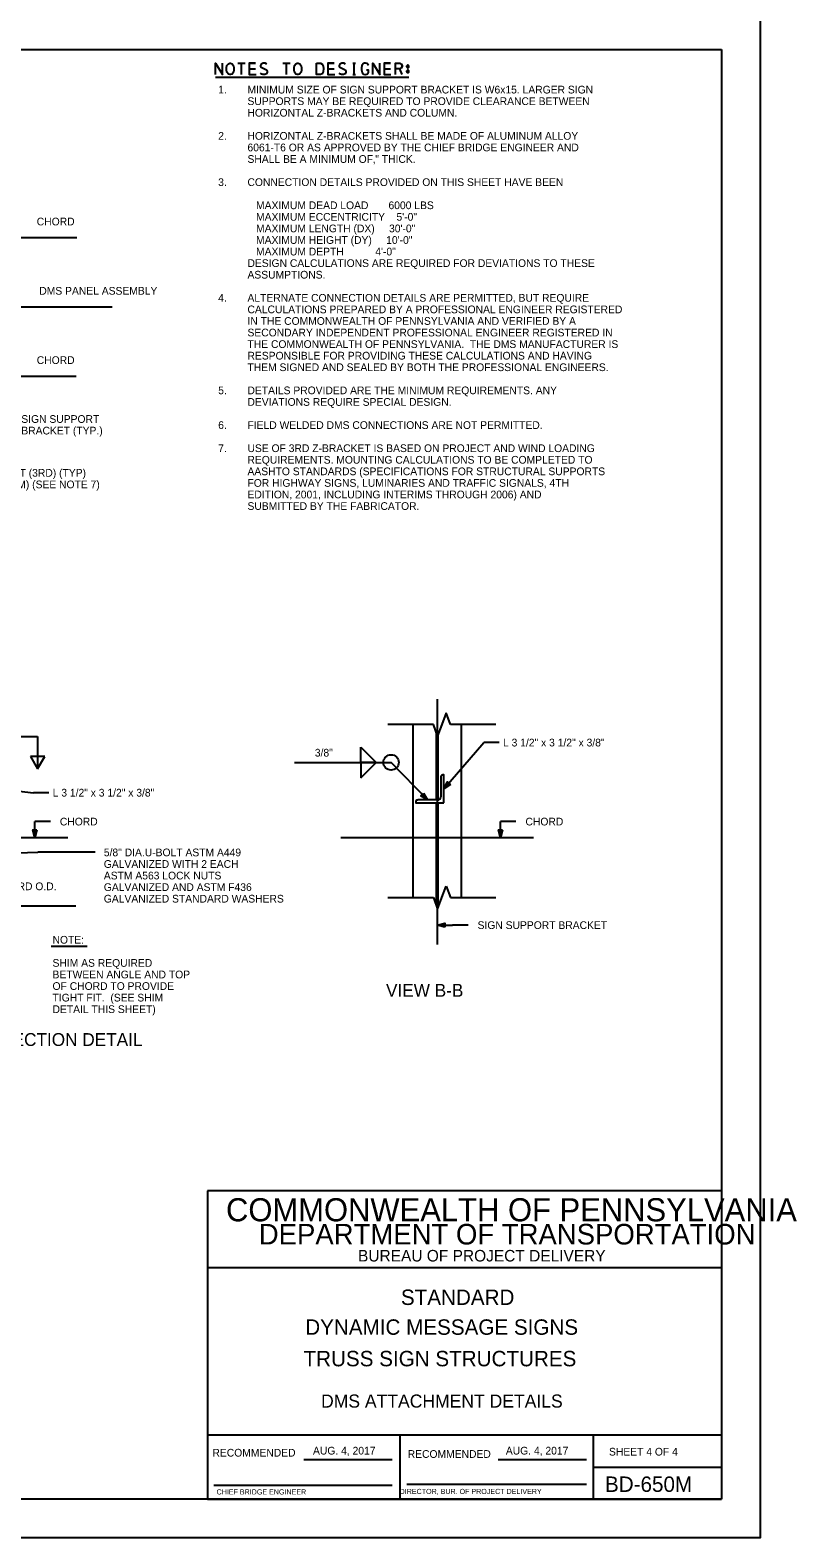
# Model space of a CAD drawing. Extents: x 3831399 to 3833095, y 499014 to 500202.
# Drawn here: x 3832797 to 3833095, y 499014 to 499601 of the extents above; entities that cross this region are included whole.
import ezdxf

# ---------------------------------------------------------------- set-up
doc = ezdxf.new("R2010")
doc.units = 0
for name, color, linetype in [('10', 7, 'Continuous'), ('2', 7, 'Continuous'), ('CNTR', 7, 'Continuous'), ('Default', 7, 'Continuous'), ('DIM TXT', 7, 'Continuous'), ('PLT-BNDY', 7, 'Continuous'), ('structure', 7, 'Continuous')]:
    doc.layers.add(name, color=color, linetype=linetype)

msp = doc.modelspace()

# ---------------------------------------------------------------- linework, layer by layer
at = {"layer": '2'}
for p, q in [((3832280.16, 499593.03), (3833066.16, 499593.03)), ((3833066.16, 499593.03), (3833066.16, 499029.03)), ((3833066.16, 499149.03), (3832866.16, 499149.03)), ((3832866.16, 499149.03), (3832866.16, 499029.03)), ((3833066.16, 499119.03), (3832866.16, 499119.03)), ((3833066.16, 499054.03), (3832866.16, 499054.03)), ((3832941.16, 499029.03), (3832941.16, 499054.03)), ((3833016.16, 499054.03), (3833016.16, 499029.03)), ((3832903.62, 499044.53), (3832938.03, 499044.53)), ((3832979.24, 499044.53), (3833013.65, 499044.53)), ((3833016.16, 499041.53), (3833066.16, 499041.53)), ((3832868.66, 499034.53), (3832938.03, 499034.53)), ((3832943.79, 499034.9), (3833013.65, 499034.9)), ((3833066.16, 499029.03), (3832280.16, 499029.03)), ((3832866.16, 499029.03), (3833066.16, 499029.03))]:
    msp.add_line(p, q, dxfattribs=at)
at = {"layer": 'CNTR'}
for p, q in [((3832528.61, 499519.83), (3832815.35, 499519.83)), ((3832528.61, 499492.88), (3832829.18, 499492.88)), ((3832528.61, 499465.92), (3832815.12, 499465.92)), ((3832955.53, 499340.29), (3832955.53, 499244.81)), ((3832685.4, 499286.41), (3832811.96, 499286.41)), ((3832918.03, 499286.41), (3832993.03, 499286.41))]:
    msp.add_line(p, q, dxfattribs=at)
at = {"layer": 'Default'}
for p, q in [((3832797.4, 499318), (3832800.15, 499313.23)), ((3832802.9, 499318), (3832797.4, 499318)), ((3832800.15, 499313.23), (3832802.9, 499318))]:
    msp.add_line(p, q, dxfattribs=at)
at = {"layer": 'DIM TXT'}
for p, q in [((3832878.01, 499587.65), (3832880.91, 499587.65)), ((3832879.46, 499583.28), (3832879.46, 499587.65)), ((3832879.46, 499583.28), (3832879.46, 499587.65)), ((3832882.39, 499587.65), (3832884.9, 499587.65)), ((3832895.51, 499587.65), (3832898.41, 499587.65)), ((3832896.96, 499583.28), (3832896.96, 499587.65)), ((3832896.96, 499583.28), (3832896.96, 499587.65)), ((3832913.01, 499587.65), (3832915.53, 499587.65)), ((3832922.73, 499587.65), (3832923.76, 499587.65)), ((3832923.24, 499583.28), (3832923.24, 499587.65)), ((3832934.89, 499587.65), (3832937.4, 499587.65)), ((3832869.26, 499582.28), (3832944.57, 499582.28)), ((3832882.39, 499585.48), (3832884.9, 499585.48)), ((3832882.39, 499585.48), (3832884.9, 499585.48)), ((3832913.01, 499585.48), (3832915.53, 499585.48)), ((3832913.01, 499585.48), (3832915.53, 499585.48)), ((3832922.73, 499583.28), (3832923.76, 499583.28)), ((3832934.89, 499585.48), (3832937.4, 499585.48)), ((3832934.89, 499585.48), (3832937.4, 499585.48)), ((3832941.98, 499583.28), (3832940.98, 499585.51)), ((3832959.06, 499334.99), (3832957.39, 499330.48)), ((3832960.72, 499330.48), (3832959.06, 499334.99)), ((3832954.05, 499330.48), (3832936.37, 499330.48)), ((3832955.72, 499325.97), (3832954.05, 499330.48)), ((3832957.39, 499330.48), (3832955.72, 499325.97)), ((3832978.4, 499330.48), (3832960.72, 499330.48)), ((3832787.65, 499325.73), (3832800.15, 499325.73)), ((3832800.15, 499325.73), (3832800.15, 499313.23)), ((3832958.13, 499305.36), (3832973.63, 499323.39)), ((3832979.63, 499323.39), (3832973.63, 499323.39)), ((3832925.85, 499321.67), (3832931.85, 499315.67)), ((3832925.85, 499315.67), (3832925.85, 499321.67)), ((3832900.11, 499315.67), (3832937.61, 499315.67)), ((3832931.85, 499315.67), (3832925.85, 499315.67)), ((3832925.85, 499309.67), (3832931.85, 499315.67)), ((3832931.85, 499315.67), (3832925.85, 499315.67)), ((3832925.85, 499315.67), (3832925.85, 499309.67)), ((3832951.82, 499301.06), (3832937.61, 499315.67)), ((3832777.66, 499306.31), (3832798.52, 499303.9)), ((3832804.51, 499303.9), (3832798.52, 499303.9)), ((3832799.1, 499286.41), (3832799.1, 499292.66)), ((3832805.1, 499292.66), (3832799.1, 499292.66)), ((3832980.16, 499286.41), (3832980.16, 499292.66)), ((3832986.16, 499292.66), (3832980.16, 499292.66)), ((3832782.09, 499280.23), (3832800.26, 499280.75)), ((3832822.52, 499280.75), (3832800.26, 499280.75)), ((3832957.39, 499263.08), (3832959.06, 499267.59)), ((3832959.06, 499267.59), (3832960.72, 499263.08)), ((3832814.96, 499259.75), (3832767.85, 499259.75)), ((3832936.37, 499263.08), (3832954.05, 499263.08)), ((3832954.05, 499263.08), (3832955.72, 499258.57)), ((3832955.72, 499258.57), (3832957.39, 499263.08)), ((3832960.72, 499263.08), (3832978.4, 499263.08)), ((3832955.53, 499252.33), (3832961.53, 499252.33)), ((3832967.53, 499252.33), (3832961.53, 499252.33)), ((3832805.41, 499244.16), (3832819.41, 499244.16))]:
    msp.add_line(p, q, dxfattribs=at)
for points in [[(3832869.26, 499583.28), (3832869.26, 499587.65), (3832871.99, 499583.28), (3832871.99, 499587.65)], [(3832874.88, 499587.65), (3832875.22, 499587.65), (3832875.81, 499587.41), (3832876.36, 499586.69), (3832876.5, 499585.82), (3832876.5, 499585.03), (3832876.36, 499584.17), (3832875.77, 499583.45), (3832875.22, 499583.28), (3832874.88, 499583.28), (3832874.36, 499583.45), (3832873.78, 499584.17), (3832873.64, 499585.03), (3832873.64, 499585.82), (3832873.78, 499586.72), (3832874.36, 499587.44), (3832874.88, 499587.65)], [(3832884.9, 499587.65), (3832882.39, 499587.65), (3832882.39, 499583.28), (3832885.08, 499583.28)], [(3832889.28, 499587.34), (3832888.59, 499587.65), (3832887.8, 499587.65), (3832887.07, 499587.34), (3832886.76, 499586.79), (3832886.76, 499586.58), (3832887.11, 499586.07), (3832889.11, 499585.03), (3832889.45, 499584.55), (3832889.42, 499584.14), (3832889.11, 499583.59), (3832888.52, 499583.28), (3832887.69, 499583.28), (3832887.31, 499583.41), (3832886.76, 499583.79)], [(3832901.13, 499587.65), (3832901.47, 499587.65), (3832902.06, 499587.41), (3832902.61, 499586.69), (3832902.75, 499585.82), (3832902.75, 499585.03), (3832902.61, 499584.17), (3832902.02, 499583.45), (3832901.47, 499583.28), (3832901.13, 499583.28), (3832900.61, 499583.45), (3832900.03, 499584.17), (3832899.89, 499585.03), (3832899.89, 499585.82), (3832900.03, 499586.72), (3832900.61, 499587.44), (3832901.13, 499587.65)], [(3832908.64, 499587.65), (3832910.22, 499587.65), (3832910.81, 499587.34), (3832911.19, 499586.58), (3832911.36, 499585.58), (3832911.15, 499584.34), (3832910.77, 499583.59), (3832910.22, 499583.28), (3832908.64, 499583.28), (3832908.64, 499587.65)], [(3832915.53, 499587.65), (3832913.01, 499587.65), (3832913.01, 499583.28), (3832915.7, 499583.28)], [(3832919.9, 499587.34), (3832919.21, 499587.65), (3832918.42, 499587.65), (3832917.7, 499587.34), (3832917.39, 499586.79), (3832917.39, 499586.58), (3832917.73, 499586.07), (3832919.73, 499585.03), (3832920.07, 499584.55), (3832920.04, 499584.14), (3832919.73, 499583.59), (3832919.14, 499583.28), (3832918.32, 499583.28), (3832917.94, 499583.41), (3832917.39, 499583.79)], [(3832928.86, 499586.79), (3832928.27, 499587.51), (3832927.72, 499587.65), (3832927.31, 499587.65), (3832926.86, 499587.51), (3832926.28, 499586.79), (3832926.14, 499585.86), (3832926.14, 499585.14), (3832926.31, 499584.1), (3832926.83, 499583.41), (3832927.34, 499583.28), (3832927.72, 499583.28), (3832928.27, 499583.41), (3832928.86, 499584.14), (3832928.86, 499585), (3832928.1, 499585)], [(3832930.51, 499583.28), (3832930.51, 499587.65), (3832933.23, 499583.28), (3832933.23, 499587.65)], [(3832937.4, 499587.65), (3832934.89, 499587.65), (3832934.89, 499583.28), (3832937.57, 499583.28)], [(3832939.26, 499583.28), (3832939.26, 499587.65), (3832941.02, 499587.65), (3832941.54, 499587.48), (3832941.98, 499586.79), (3832941.98, 499586.38), (3832941.57, 499585.69), (3832941.02, 499585.51), (3832939.26, 499585.51)], [(3832944.57, 499586.31), (3832944.57, 499586.44), (3832944.53, 499586.58), (3832944.46, 499586.69), (3832944.33, 499586.79), (3832944.19, 499586.86), (3832943.98, 499586.86), (3832943.84, 499586.79), (3832943.71, 499586.65), (3832943.64, 499586.51), (3832943.64, 499586.31), (3832943.71, 499586.13), (3832943.84, 499586), (3832944.02, 499585.93), (3832944.19, 499585.93), (3832944.36, 499586), (3832944.5, 499586.13), (3832944.57, 499586.31)], [(3832944.57, 499584.41), (3832944.57, 499584.55), (3832944.53, 499584.69), (3832944.46, 499584.79), (3832944.33, 499584.89), (3832944.19, 499584.96), (3832943.98, 499584.96), (3832943.84, 499584.89), (3832943.71, 499584.76), (3832943.64, 499584.62), (3832943.64, 499584.41), (3832943.71, 499584.24), (3832943.84, 499584.1), (3832944.02, 499584.03), (3832944.19, 499584.03), (3832944.36, 499584.1), (3832944.5, 499584.24), (3832944.57, 499584.41)]]:
    msp.add_lwpolyline(points, dxfattribs=at)
for points in [[(3832960.65, 499307.14), (3832958.13, 499305.36), (3832959.51, 499308.12)], [(3832950.27, 499303.73), (3832951.82, 499301.06), (3832949.19, 499302.69)], [(3832799.85, 499289.41), (3832799.1, 499286.41), (3832798.35, 499289.41)], [(3832980.91, 499289.41), (3832980.16, 499286.41), (3832979.41, 499289.41)], [(3832958.53, 499251.58), (3832955.53, 499252.33), (3832958.53, 499253.08)]]:
    msp.add_lwpolyline(points, close=True, dxfattribs=at)
msp.add_circle((3832937.61, 499315.67), 3, dxfattribs=at)
at = {"layer": 'PLT-BNDY'}
msp.add_lwpolyline([(3832240.16, 499608.03), (3833081.16, 499608.03), (3833081.16, 499014.03), (3832240.16, 499014.03)], close=True, dxfattribs=at)
at = {"layer": 'structure'}
for p, q in [((3832946.17, 499299.89), (3832946.17, 499330.48)), ((3832964.89, 499330.48), (3832964.89, 499263.08)), ((3832955.17, 499327.46), (3832955.17, 499301.53)), ((3832955.89, 499301.53), (3832955.89, 499326.43)), ((3832946.17, 499263.08), (3832946.17, 499299.89)), ((3832955.14, 499299.89), (3832955.14, 499260.14)), ((3832955.92, 499259.12), (3832955.92, 499299.89))]:
    msp.add_line(p, q, dxfattribs=at)
for points in [[(3832956.95, 499310.04), (3832956.95, 499302.23)], [(3832958.13, 499299.89), (3832958.13, 499310.82), (3832957.74, 499310.82)], [(3832947.19, 499300.27), (3832947.19, 499299.89), (3832958.13, 499299.89)], [(3832955.78, 499301.06), (3832947.97, 499301.06)]]:
    msp.add_lwpolyline(points, dxfattribs=at)
for centre, radius, start, end in [((3832957.74, 499310.04), 0.785, 90, 180), ((3832947.97, 499300.27), 0.785, 90, 180), ((3832955.78, 499302.23), 1.17, 270, 0)]:
    msp.add_arc(centre, radius, start, end, dxfattribs=at)

# ---------------------------------------------------------------- texts
at = {"layer": '10'}
for s, height, p in [('STANDARD ', 6, (3832941.43, 499104.62)), ('DYNAMIC MESSAGE SIGNS', 6, (3832904.23, 499093.02)), ('TRUSS SIGN STRUCTURES', 6, (3832903.56, 499080.76)), ('DMS ATTACHMENT DETAILS', 5.1, (3832910.38, 499064.69))]:
    msp.add_text(s, height=height, dxfattribs=at).set_placement(p)
at = {"layer": '2'}
for s, height, p in [('COMMONWEALTH OF PENNSYLVANIA', 9, (3832873.41, 499137.15)), ('DEPARTMENT OF TRANSPORTATION', 8.0002, (3832886.16, 499128.15)), ('BUREAU OF PROJECT DELIVERY', 4.5, (3832924.75, 499121.53)), ('AUG. 4, 2017', 3, (3832907.24, 499046.44)), ('AUG. 4, 2017', 3, (3832982.24, 499046.44)), ('SHEET 4 OF 4', 3, (3833022.36, 499046.04)), ('BD-650M', 6, (3833020.79, 499031.9)), ('CHIEF BRIDGE ENGINEER', 2.0002, (3832869.75, 499030.9)), ('   DIRECTOR, BUR. OF PROJECT DELIVERY', 2.0002, (3832938.63, 499031.08))]:
    msp.add_text(s, height=height, dxfattribs=at).set_placement(p)
for p in [(3832868.14, 499045.64), (3832944.07, 499045.15)]:
    msp.add_text('RECOMMENDED', height=3, rotation=360, dxfattribs=at).set_placement(p)
at = {"layer": 'Default'}
for s, height, p in [('VIEW B-B', 5, (3832935.63, 499224.52)), ('ALTERNATE PANEL CONNECTION DETAIL', 4.9999, (3832705.7, 499205.37))]:
    msp.add_text(s, height=height, dxfattribs=at).set_placement(p)
at = {"layer": 'DIM TXT'}
for s, height, p in [(' 1.', 3, (3832869.26, 499575.9)), ('MINIMUM SIZE OF SIGN SUPPORT BRACKET IS W6x15. LARGER SIGN ', 2.9999, (3832881.76, 499575.9)), ('SUPPORTS MAY BE REQUIRED TO PROVIDE CLEARANCE BETWEEN ', 2.9999, (3832881.76, 499571.4)), ('HORIZONTAL Z-BRACKETS AND COLUMN.', 2.9999, (3832881.76, 499566.9)), (' 2.', 3, (3832869.26, 499557.9)), ('HORIZONTAL Z-BRACKETS SHALL BE MADE OF ALUMINUM ALLOY ', 2.9999, (3832881.76, 499557.9)), ('SHALL BE A MINIMUM OF‚" THICK.', 2.9999, (3832881.76, 499548.9)), ('6061-T6 OR AS APPROVED BY THE CHIEF BRIDGE ENGINEER AND ', 2.9999, (3832881.76, 499553.4)), (' 3.', 3, (3832869.26, 499539.9)), ('CONNECTION DETAILS PROVIDED ON THIS SHEET HAVE BEEN ', 2.9999, (3832881.76, 499539.9)), ('   MAXIMUM DEAD LOAD       6000 LBS', 2.9999, (3832881.76, 499530.9)), ('   MAXIMUM ECCENTRICITY    5\'-0"', 2.9999, (3832881.76, 499526.4)), ('  CHORD', 3, (3832797.59, 499524.58)), ('   MAXIMUM LENGTH (DX)     30\'-0"', 2.9999, (3832881.76, 499521.9)), ('   MAXIMUM HEIGHT (DY)     10\'-0"', 2.9999, (3832881.76, 499517.4)), ('DESIGN CALCULATIONS ARE REQUIRED FOR DEVIATIONS TO THESE ', 2.9999, (3832881.76, 499508.4)), ('   MAXIMUM DEPTH           4\'-0"', 2.9999, (3832881.76, 499512.9)), ('ASSUMPTIONS.', 2.9999, (3832881.76, 499503.9)), ('  DMS PANEL ASSEMBLY', 2.9999, (3832798.57, 499497.63)), (' 4.', 3, (3832869.26, 499494.9)), ('ALTERNATE CONNECTION DETAILS ARE PERMITTED, BUT REQUIRE ', 2.9999, (3832881.76, 499494.9)), ('CALCULATIONS PREPARED BY A PROFESSIONAL ENGINEER REGISTERED ', 2.9999, (3832881.76, 499490.4)), ('IN THE COMMONWEALTH OF PENNSYLVANIA AND VERIFIED BY A ', 2.9999, (3832881.76, 499485.9)), ('SECONDARY INDEPENDENT PROFESSIONAL ENGINEER REGISTERED IN ', 2.9999, (3832881.76, 499481.4)), ('THE COMMONWEALTH OF PENNSYLVANIA.  THE DMS MANUFACTURER IS ', 2.9999, (3832881.76, 499476.9)), ('RESPONSIBLE FOR PROVIDING THESE CALCULATIONS AND HAVING ', 2.9999, (3832881.76, 499472.4)), ('  CHORD', 3, (3832797.59, 499470.67)), ('THEM SIGNED AND SEALED BY BOTH THE PROFESSIONAL ENGINEERS.', 2.9999, (3832881.76, 499467.9)), (' 5.', 3, (3832869.26, 499458.9)), ('DETAILS PROVIDED ARE THE MINIMUM REQUIREMENTS. ANY ', 2.9999, (3832881.76, 499458.9)), ('DEVIATIONS REQUIRE SPECIAL DESIGN.', 2.9999, (3832881.76, 499454.4)), ('SIGN SUPPORT ', 2.9999, (3832793.81, 499447.76)), ('BRACKET (TYP.)', 2.9999, (3832793.81, 499443.26)), (' 6.', 3, (3832869.26, 499445.4)), ('FIELD WELDED DMS CONNECTIONS ARE NOT PERMITTED.', 2.9999, (3832881.76, 499445.4)), (' 7.', 3, (3832869.26, 499436.4)), ('USE OF 3RD Z-BRACKET IS BASED ON PROJECT AND WIND LOADING ', 2.9999, (3832881.76, 499436.4)), ('REQUIREMENTS. MOUNTING CALCULATIONS TO BE COMPLETED TO ', 2.9999, (3832881.76, 499431.9)), ('Z-BRACKET (3RD) (TYP)', 2.9999, (3832772.84, 499426.82)), ('AASHTO STANDARDS (SPECIFICATIONS FOR STRUCTURAL SUPPORTS ', 2.9999, (3832881.76, 499427.4)), ('(ALUMINUM) (SEE NOTE 7)', 2.9999, (3832772.84, 499422.32)), ('FOR HIGHWAY SIGNS, LUMINARIES AND TRAFFIC SIGNALS, 4TH ', 2.9999, (3832881.76, 499422.9)), ('SUBMITTED BY THE FABRICATOR. ', 2.9999, (3832881.76, 499413.9)), ('EDITION, 2001, INCLUDING INTERIMS THROUGH 2006) AND ', 2.9999, (3832881.76, 499418.4)), ('L 3 1/2" x 3 1/2" x 3/8"', 2.9999, (3832981.13, 499321.89)), ('3/8"', 3, (3832907.95, 499317.96)), ('L 3 1/2" x 3 1/2" x 3/8"', 2.9999, (3832806.01, 499302.4)), ('  CHORD', 3, (3832806.57, 499291.16)), ('  CHORD', 3, (3832987.64, 499291.16)), ('5/8" DIA.U-BOLT ASTM A449', 2.9999, (3832825.9, 499279.16)), ('GALVANIZED WITH 2 EACH', 2.9999, (3832825.9, 499274.66)), ('ASTM A563 LOCK NUTS', 2.9999, (3832825.9, 499270.16)), ('1/2x CHORD O.D.', 2.9999, (3832774.74, 499265.98)), ('GALVANIZED AND ASTM F436', 2.9999, (3832825.9, 499265.66)), ('GALVANIZED STANDARD WASHERS', 2.9999, (3832825.9, 499261.16)), ('  SIGN SUPPORT BRACKET', 2.9999, (3832969.01, 499250.88)), ('NOTE:', 3, (3832805.95, 499245.18)), ('SHIM AS REQUIRED ', 2.9999, (3832805.95, 499236.18)), ('BETWEEN ANGLE AND TOP ', 2.9999, (3832805.95, 499231.68)), ('OF CHORD TO PROVIDE ', 2.9999, (3832805.95, 499227.18)), ('TIGHT FIT.  (SEE SHIM ', 2.9999, (3832805.95, 499222.68)), ('DETAIL THIS SHEET) ', 2.9999, (3832805.95, 499218.18))]:
    msp.add_text(s, height=height, dxfattribs=at).set_placement(p)

doc.saveas('drawing.dxf')
